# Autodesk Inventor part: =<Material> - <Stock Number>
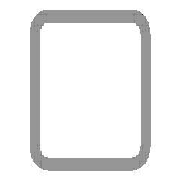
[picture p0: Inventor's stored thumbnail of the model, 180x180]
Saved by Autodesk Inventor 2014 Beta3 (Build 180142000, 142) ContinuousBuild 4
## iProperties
IsCustomPart: 1
_CCFamilyMember: 9
_CCFamilyDisplayName: ANSI AISC (Square) - Tube
_FrameMemberDoc: Frame Member File
_Version: 15.0.0
_GetPNFromCC: 1
Created: 2011-01
Part Number: =<Material> - <Stock Number>
Material: Steel, Mild
Description: Tube
Document SubType Name: Modeling
Standard: ANSI
Designer: Beta-8540w
Standards Organization: ANSI
Language: en-US
Size Designation: 3x3x3/16
Categories: <MemberInstance><Categories><Category DisplayName="Structural Shapes" InternalName="089c4875-fa83-4c05-b084-43b9cc11f5ed" Mnemonic="GRDR"><CategoryParameter Dis
Stock Number: 3x3x3/16
Density: 7.86 g/cm^3
Appearance: Steel
G_L: 58.775 in
G_W: 3.000 in
G_H: 3.000 in
+F1DD31D7-8EA7-4030-B73F-B4109CE49B1F+CUTDETAIL1: Cut
Author: Beta-8540w
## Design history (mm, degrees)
node "Start plane"
node "End plane"
sketch "Sketch"
  geometry: L1 (-38.1, -28.575)-(-38.1, 28.575); L2 (-28.575, 38.1)-(28.575, 38.1); L3 (38.1, 28.575)-(38.1, -28.575); L4 (28.575, -38.1)-(-28.575, -38.1); L5 (-28.575, 33.337)-(28.575, 33.338); L6 (33.338, 28.575)-(33.338, -28.575); L7 (28.575, -33.337)-(-28.575, -33.338); L8 (-33.338, -28.575)-(-33.338, 28.575); L9 (0, 56.102)-(0, -56.102) reference; L10 (-56.102, 0)-(56.102, 0) reference; A1 r 9.525 centre (-28.575, -28.575) between (-38.1, -28.575) and (-28.575, -38.1); A2 r 9.525 centre (-28.575, 28.575) between (-28.575, 38.1) and (-38.1, 28.575); A3 r 9.525 centre (28.575, 28.575) between (38.1, 28.575) and (28.575, 38.1); A4 r 9.525 centre (28.575, -28.575) between (28.575, -38.1) and (38.1, -28.575); A5 r 4.763 centre (-28.575, 28.575) between (-28.575, 33.337) and (-33.338, 28.575); A6 r 4.763 centre (28.575, 28.575) between (33.338, 28.575) and (28.575, 33.338); A7 r 4.763 centre (28.575, -28.575) between (28.575, -33.337) and (33.338, -28.575); A8 r 4.763 centre (-28.575, -28.575) between (-33.338, -28.575) and (-28.575, -33.338)
  constraints: 16 end point, 16 point on circle, 8 centre point, 8 tangent, 4 parallel, 3 equal radius, 2 perpendicular, 7 other
  dimensions: "d10" = 76.2 distance between parallel lines of L2 L4 (= G_H); "d11" = 76.2 distance between parallel lines of L1 L3 (= G_W); "d12" = 4.7625 distance between parallel lines of L3 L6 (= G_T); "d15" = 38.1 distance between parallel lines of L2 L10 (= 0.5 x d10); "d16" = 38.1 distance between parallel lines of L9 L3 (= 0.5 x d11); "d17" = 9.525 radius of A1 (= G_IR)
extrude "Body" new body sketch "Sketch" stored distance "d3" = 1492.89148 (= G_L); taper "d4" = 0 deg
node "Driven Length"
  sketch "Sketch3"
    geometry: L1 (0, 0)-(10, 0) reference
    constraints: 2 end point, 1 horizontal
  workplane "Work Plane3"
  sketch "Sketch4"
    geometry: L1 (-2, 31.109)-(12, 31.109) reference; L2 (-2, 1524)-(12, 1524) reference
    dimensions: "d19" = 1492.89148 distance between parallel lines of L1 L2 (derived)
workplane "Work Plane4"
split "Split1"
body "Solid1"
other parameters: "G_W" = 76.2 [user parameter; used in 1 equation term], "G_H" = 76.2 [user parameter; used in 1 equation term], "G_T" = 4.7625 [user parameter; used in 1 equation term], "G_IR" = 9.525 [user parameter; used in 1 equation term], "G_L" = 1492.89148 (= d19) [user parameter; used in 1 equation term], "G_OFFSET_START" = -31.10852 [user parameter; used in 1 equation term], "G_OFFSET_END" = 0 [user parameter; used in 1 equation term], "d13" = 31.10852 (= -G_OFFSET_START), "d14" = 1524 (= G_OFFSET_END + B_L), "B_L" = 1524 [user parameter; used in 1 equation term], "d18" = 90 deg
